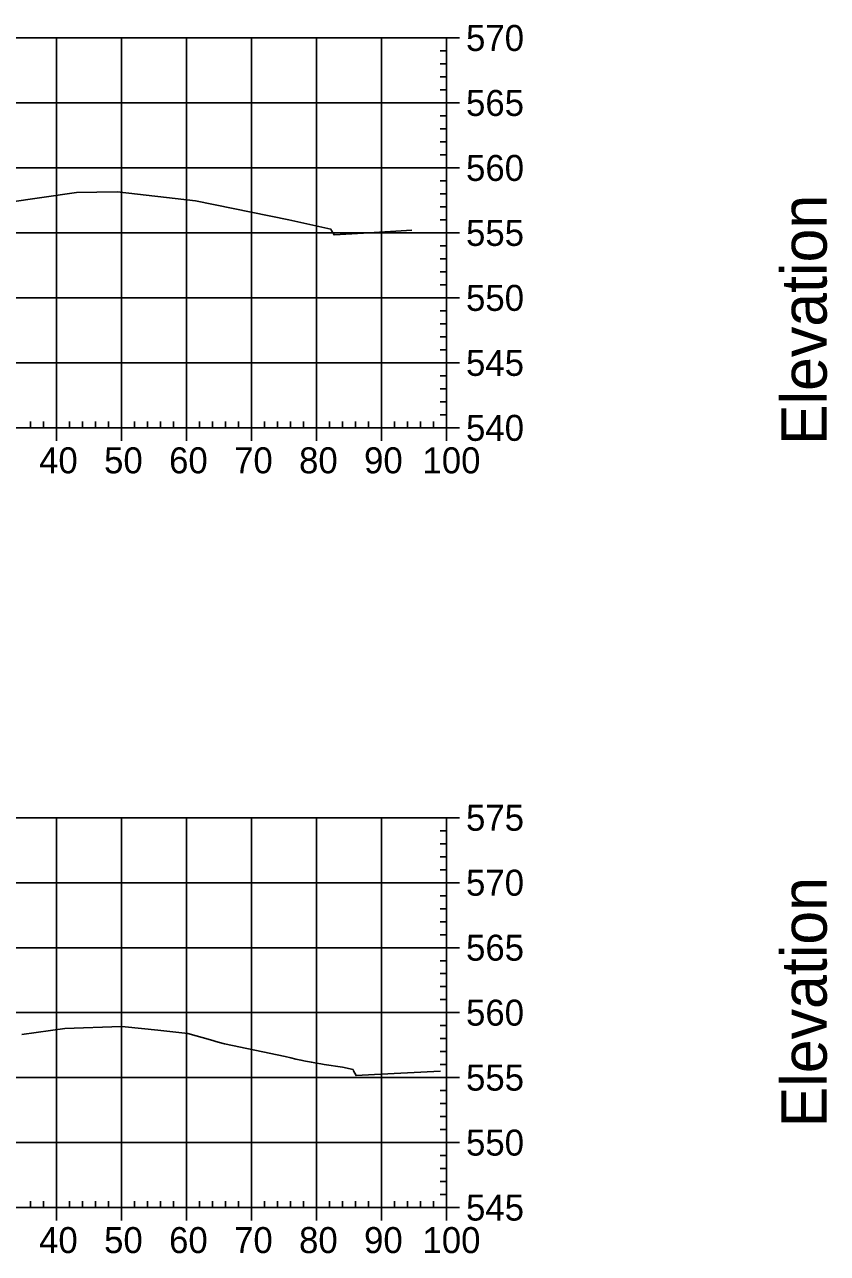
# Model space of a CAD drawing. Extents: x 704834 to 709892, y 372981 to 377533.
# Drawn here: x 708990 to 709113.5, y 376753.8 to 376942.9 of the extents above; entities that cross this region are included whole.
import ezdxf

# ---------------------------------------------------------------- set-up
doc = ezdxf.new("R2010")
doc.units = 0
for name, color, linetype in [('57', 7, 'Continuous'), ('60', 7, 'Continuous'), ('Existing', 7, 'Continuous')]:
    doc.layers.add(name, color=color, linetype=linetype)

msp = doc.modelspace()

# ---------------------------------------------------------------- linework, layer by layer
at = {"layer": '57'}
for p, q in [((708854.91, 376940.82), (709054.91, 376940.82)), ((708994.91, 376880.82), (708994.91, 376940.82)), ((709004.91, 376880.82), (709004.91, 376940.82)), ((709014.91, 376880.82), (709014.91, 376940.82)), ((709024.91, 376880.82), (709024.91, 376940.82)), ((709034.91, 376880.82), (709034.91, 376940.82)), ((709044.91, 376880.82), (709044.91, 376940.82)), ((709054.91, 376880.82), (709054.91, 376940.82)), ((709054.91, 376880.82), (709054.91, 376940.82)), ((709056.91, 376940.82), (709054.91, 376940.82)), ((709054.91, 376938.82), (709053.91, 376938.82)), ((709054.91, 376936.82), (709053.91, 376936.82)), ((709054.91, 376934.82), (709053.91, 376934.82)), ((709054.91, 376932.82), (709053.91, 376932.82)), ((708854.91, 376930.82), (709054.91, 376930.82)), ((709056.91, 376930.82), (709054.91, 376930.82)), ((709054.91, 376928.82), (709053.91, 376928.82)), ((709054.91, 376926.82), (709053.91, 376926.82)), ((709054.91, 376924.82), (709053.91, 376924.82)), ((709054.91, 376922.82), (709053.91, 376922.82)), ((708854.91, 376920.82), (709054.91, 376920.82)), ((709056.91, 376920.82), (709054.91, 376920.82)), ((709054.91, 376918.82), (709053.91, 376918.82)), ((709054.91, 376916.82), (709053.91, 376916.82)), ((709054.91, 376914.82), (709053.91, 376914.82)), ((709054.91, 376912.82), (709053.91, 376912.82)), ((708854.91, 376910.82), (709054.91, 376910.82)), ((709056.91, 376910.82), (709054.91, 376910.82)), ((709054.91, 376908.82), (709053.91, 376908.82)), ((709054.91, 376906.82), (709053.91, 376906.82)), ((709054.91, 376904.82), (709053.91, 376904.82)), ((709054.91, 376902.82), (709053.91, 376902.82)), ((708854.91, 376900.82), (709054.91, 376900.82)), ((709056.91, 376900.82), (709054.91, 376900.82)), ((709054.91, 376898.82), (709053.91, 376898.82)), ((709054.91, 376896.82), (709053.91, 376896.82)), ((709054.91, 376894.82), (709053.91, 376894.82)), ((709054.91, 376892.82), (709053.91, 376892.82)), ((708854.91, 376890.82), (709054.91, 376890.82)), ((709056.91, 376890.82), (709054.91, 376890.82)), ((709054.91, 376888.82), (709053.91, 376888.82)), ((709054.91, 376886.82), (709053.91, 376886.82)), ((709054.91, 376884.82), (709053.91, 376884.82)), ((709054.91, 376882.82), (709053.91, 376882.82)), ((708854.91, 376880.82), (709054.91, 376880.82)), ((708854.91, 376880.82), (709054.91, 376880.82)), ((708990.91, 376880.82), (708990.91, 376881.82)), ((708992.91, 376880.82), (708992.91, 376881.82)), ((708994.91, 376878.82), (708994.91, 376880.82)), ((708996.91, 376880.82), (708996.91, 376881.82)), ((708998.91, 376880.82), (708998.91, 376881.82)), ((709000.91, 376880.82), (709000.91, 376881.82)), ((709002.91, 376880.82), (709002.91, 376881.82)), ((709004.91, 376878.82), (709004.91, 376880.82)), ((709006.91, 376880.82), (709006.91, 376881.82)), ((709008.91, 376880.82), (709008.91, 376881.82)), ((709010.91, 376880.82), (709010.91, 376881.82)), ((709012.91, 376880.82), (709012.91, 376881.82)), ((709014.91, 376878.82), (709014.91, 376880.82)), ((709016.91, 376880.82), (709016.91, 376881.82)), ((709018.91, 376880.82), (709018.91, 376881.82)), ((709020.91, 376880.82), (709020.91, 376881.82)), ((709022.91, 376880.82), (709022.91, 376881.82)), ((709024.91, 376878.82), (709024.91, 376880.82)), ((709026.91, 376880.82), (709026.91, 376881.82)), ((709028.91, 376880.82), (709028.91, 376881.82)), ((709030.91, 376880.82), (709030.91, 376881.82)), ((709032.91, 376880.82), (709032.91, 376881.82)), ((709034.91, 376878.82), (709034.91, 376880.82)), ((709036.91, 376880.82), (709036.91, 376881.82)), ((709038.91, 376880.82), (709038.91, 376881.82)), ((709040.91, 376880.82), (709040.91, 376881.82)), ((709042.91, 376880.82), (709042.91, 376881.82)), ((709044.91, 376878.82), (709044.91, 376880.82)), ((709046.91, 376880.82), (709046.91, 376881.82)), ((709048.91, 376880.82), (709048.91, 376881.82)), ((709050.91, 376880.82), (709050.91, 376881.82)), ((709052.91, 376880.82), (709052.91, 376881.82)), ((709054.91, 376878.82), (709054.91, 376880.82)), ((709056.91, 376880.82), (709054.91, 376880.82)), ((708854.91, 376820.82), (709054.91, 376820.82)), ((708994.91, 376760.82), (708994.91, 376820.82)), ((709004.91, 376760.82), (709004.91, 376820.82)), ((709014.91, 376760.82), (709014.91, 376820.82)), ((709024.91, 376760.82), (709024.91, 376820.82)), ((709034.91, 376760.82), (709034.91, 376820.82)), ((709044.91, 376760.82), (709044.91, 376820.82)), ((709054.91, 376760.82), (709054.91, 376820.82)), ((709054.91, 376760.82), (709054.91, 376820.82)), ((709056.91, 376820.82), (709054.91, 376820.82)), ((709054.91, 376818.82), (709053.91, 376818.82)), ((709054.91, 376816.82), (709053.91, 376816.82)), ((709054.91, 376814.82), (709053.91, 376814.82)), ((709054.91, 376812.82), (709053.91, 376812.82)), ((708854.91, 376810.82), (709054.91, 376810.82)), ((709056.91, 376810.82), (709054.91, 376810.82)), ((709054.91, 376808.82), (709053.91, 376808.82)), ((709054.91, 376806.82), (709053.91, 376806.82)), ((709054.91, 376804.82), (709053.91, 376804.82)), ((709054.91, 376802.82), (709053.91, 376802.82)), ((708854.91, 376800.82), (709054.91, 376800.82)), ((709056.91, 376800.82), (709054.91, 376800.82)), ((709054.91, 376798.82), (709053.91, 376798.82)), ((709054.91, 376796.82), (709053.91, 376796.82)), ((709054.91, 376794.82), (709053.91, 376794.82)), ((709054.91, 376792.82), (709053.91, 376792.82)), ((708854.91, 376790.82), (709054.91, 376790.82)), ((709056.91, 376790.82), (709054.91, 376790.82)), ((709054.91, 376788.82), (709053.91, 376788.82)), ((709054.91, 376786.82), (709053.91, 376786.82)), ((709054.91, 376784.82), (709053.91, 376784.82)), ((709054.91, 376782.82), (709053.91, 376782.82)), ((708854.91, 376780.82), (709054.91, 376780.82)), ((709056.91, 376780.82), (709054.91, 376780.82)), ((709054.91, 376778.82), (709053.91, 376778.82)), ((709054.91, 376776.82), (709053.91, 376776.82)), ((709054.91, 376774.82), (709053.91, 376774.82)), ((709054.91, 376772.82), (709053.91, 376772.82)), ((708854.91, 376770.82), (709054.91, 376770.82)), ((709056.91, 376770.82), (709054.91, 376770.82)), ((709054.91, 376768.82), (709053.91, 376768.82)), ((709054.91, 376766.82), (709053.91, 376766.82)), ((709054.91, 376764.82), (709053.91, 376764.82)), ((708990.91, 376760.82), (708990.91, 376761.82)), ((708992.91, 376760.82), (708992.91, 376761.82)), ((708996.91, 376760.82), (708996.91, 376761.82)), ((708998.91, 376760.82), (708998.91, 376761.82)), ((709000.91, 376760.82), (709000.91, 376761.82)), ((709002.91, 376760.82), (709002.91, 376761.82)), ((709006.91, 376760.82), (709006.91, 376761.82)), ((709008.91, 376760.82), (709008.91, 376761.82)), ((709010.91, 376760.82), (709010.91, 376761.82)), ((709012.91, 376760.82), (709012.91, 376761.82)), ((709016.91, 376760.82), (709016.91, 376761.82)), ((709018.91, 376760.82), (709018.91, 376761.82)), ((709020.91, 376760.82), (709020.91, 376761.82)), ((709022.91, 376760.82), (709022.91, 376761.82)), ((709026.91, 376760.82), (709026.91, 376761.82)), ((709028.91, 376760.82), (709028.91, 376761.82)), ((709030.91, 376760.82), (709030.91, 376761.82)), ((709032.91, 376760.82), (709032.91, 376761.82)), ((709036.91, 376760.82), (709036.91, 376761.82)), ((709038.91, 376760.82), (709038.91, 376761.82)), ((709040.91, 376760.82), (709040.91, 376761.82)), ((709042.91, 376760.82), (709042.91, 376761.82)), ((709046.91, 376760.82), (709046.91, 376761.82)), ((709048.91, 376760.82), (709048.91, 376761.82)), ((709050.91, 376760.82), (709050.91, 376761.82)), ((709052.91, 376760.82), (709052.91, 376761.82)), ((709054.91, 376762.82), (709053.91, 376762.82)), ((708854.91, 376760.82), (709054.91, 376760.82)), ((708854.91, 376760.82), (709054.91, 376760.82)), ((708994.91, 376758.82), (708994.91, 376760.82)), ((709004.91, 376758.82), (709004.91, 376760.82)), ((709014.91, 376758.82), (709014.91, 376760.82)), ((709024.91, 376758.82), (709024.91, 376760.82)), ((709034.91, 376758.82), (709034.91, 376760.82)), ((709044.91, 376758.82), (709044.91, 376760.82)), ((709054.91, 376758.82), (709054.91, 376760.82)), ((709056.91, 376760.82), (709054.91, 376760.82))]:
    msp.add_line(p, q, dxfattribs=at)
at = {"layer": 'Existing'}
for points in [[(708987.3, 376915.5), (708997.97, 376917.02), (709004.21, 376917.13), (709016.27, 376915.75), (709030.63, 376912.83), (709037.12, 376911.39), (709037.23, 376911.18), (709037.6, 376910.51), (709042.12, 376910.76), (709049.59, 376911.26)], [(708989.57, 376787.44), (708996.19, 376788.38), (709004.84, 376788.71), (709005.46, 376788.65), (709010.49, 376788.11), (709015.12, 376787.61), (709018.58, 376786.64), (709019.8, 376786.3), (709020.77, 376786.02), (709030.07, 376784.06), (709030.93, 376783.86), (709031.74, 376783.67), (709032.5, 376783.51), (709033.21, 376783.36), (709034.11, 376783.19), (709034.89, 376783.05), (709035.55, 376782.94), (709036.09, 376782.86), (709038.89, 376782.44), (709040.53, 376782.05), (709040.6, 376781.89), (709040.99, 376781.13), (709043.84, 376781.31), (709053.99, 376781.81)]]:
    msp.add_lwpolyline(points, dxfattribs=at)

# ---------------------------------------------------------------- texts
at = {"layer": '57'}
for s, p in [('570', (709057.91, 376938.82)), ('565', (709057.91, 376928.82)), ('560', (709057.91, 376918.82)), ('555', (709057.91, 376908.82)), ('550', (709057.91, 376898.82)), ('545', (709057.91, 376888.82)), ('540', (709057.91, 376878.82)), ('40', (708992.22, 376873.82)), ('50', (709002.22, 376873.82)), ('60', (709012.22, 376873.82)), ('70', (709022.22, 376873.82)), ('80', (709032.22, 376873.82)), ('90', (709042.22, 376873.82)), ('100', (709051.21, 376873.82)), ('575', (709057.91, 376818.82)), ('570', (709057.91, 376808.82)), ('565', (709057.91, 376798.82)), ('560', (709057.91, 376788.82)), ('555', (709057.91, 376778.82)), ('550', (709057.91, 376768.82)), ('545', (709057.91, 376758.82)), ('40', (708992.22, 376753.82)), ('50', (709002.22, 376753.82)), ('60', (709012.22, 376753.82)), ('70', (709022.22, 376753.82)), ('80', (709032.22, 376753.82)), ('90', (709042.22, 376753.82)), ('100', (709051.21, 376753.82))]:
    msp.add_text(s, height=4, dxfattribs=at).set_placement(p)
at = {"layer": '60'}
for p in [(709113.41, 376878.18), (709113.41, 376773.18)]:
    msp.add_text('Elevation', height=7, rotation=90, dxfattribs=at).set_placement(p)

doc.saveas('drawing.dxf')
